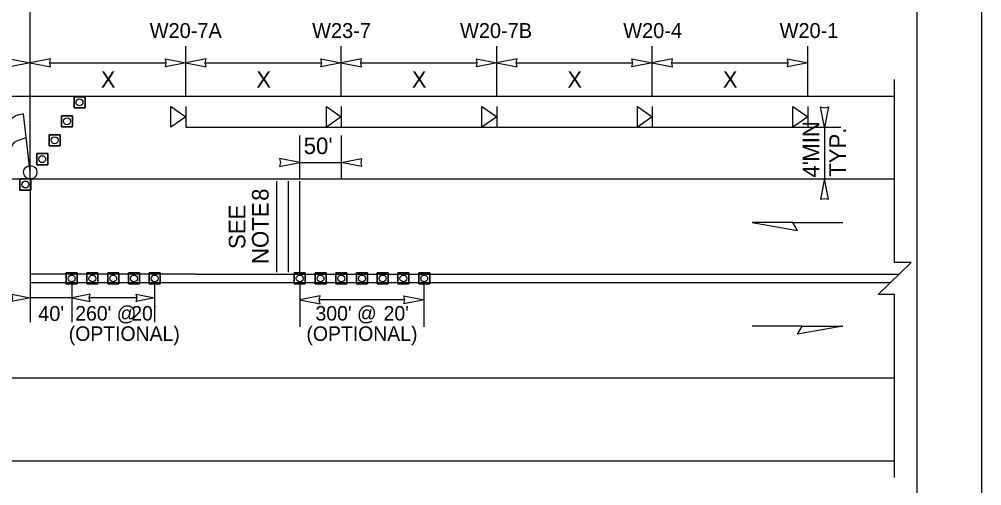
# Model space of a CAD drawing. Extents: x 99999.1 to 100095.7, y 99995 to 100010.7.
# Drawn here: x 100011.42 to 100016.062, y 100005.612 to 100007.863 of the extents above; entities that cross this region are included whole.
import ezdxf

# ---------------------------------------------------------------- set-up
doc = ezdxf.new("R2010")
doc.units = 0
for name, color, linetype in [('RD_ED_ShoulderPavedEdge', 7, 'Continuous'), ('RD_MK_LineDblYellowCenter', 7, 'Continuous'), ('RD_MK_LineEdgeWhite', 7, 'Continuous'), ('RD_MK_LineNoPass', 7, 'Continuous'), ('RD_MK_LineSkipCenter', 7, 'Continuous'), ('SH_GI_PlotLimits', 7, 'Continuous'), ('SH_GI_SheetBorder', 7, 'Continuous'), ('TR_SN_ConstructionSigns', 7, 'Continuous'), ('TR_WZ_FlaggingStation', 7, 'Continuous'), ('TR_WZ_PortableSignMountBlk-Org', 7, 'Continuous'), ('TR_WZ_TrafficCone', 7, 'Continuous'), ('TR_WZ_WorkZoneDetails', 7, 'Continuous'), ('TR_WZ_WorkZoneTextCurrent', 7, 'Continuous')]:
    doc.layers.add(name, color=color, linetype=linetype)

msp = doc.modelspace()

# ---------------------------------------------------------------- linework, layer by layer
at = {"layer": 'RD_ED_ShoulderPavedEdge'}
for p, q in [((100000.1076, 100007.4923), (100015.6424, 100007.4923)), ((100000.1076, 100005.7323), (100015.6424, 100005.7323))]:
    msp.add_line(p, q, dxfattribs=at)
at = {"layer": 'RD_MK_LineDblYellowCenter'}
for p, q in [((100012.2733, 100006.6323), (100015.6631, 100006.6323)), ((100012.2733, 100006.5923), (100015.6218, 100006.5923))]:
    msp.add_line(p, q, dxfattribs=at)
at = {"layer": 'RD_MK_LineEdgeWhite'}
for p, q in [((100000.1076, 100007.0923), (100015.6424, 100007.0923)), ((100000.1076, 100006.1323), (100015.6424, 100006.1323))]:
    msp.add_line(p, q, dxfattribs=at)
at = {"layer": 'RD_MK_LineNoPass'}
msp.add_line((100011.4733, 100006.5923), (100012.2733, 100006.5923), dxfattribs=at)
at = {"layer": 'RD_MK_LineSkipCenter'}
msp.add_lwpolyline([(100012.2733, 100006.6323), (100011.4733, 100006.6323)], dxfattribs=at)
at = {"layer": 'SH_GI_PlotLimits'}
msp.add_lwpolyline([(99999.0625, 99999.6875), (100016.0625, 99999.6875), (100016.0625, 100010.6875), (99999.0625, 100010.6875)], close=True, dxfattribs=at)
at = {"layer": 'SH_GI_SheetBorder'}
msp.add_line((100015.75, 100010.375), (100015.75, 100000), dxfattribs=at)
at = {"layer": 'TR_WZ_FlaggingStation'}
for p, q in [((100011.4543, 100007.2917), (100011.4413, 100007.4061)), ((100011.4733, 100007.1248), (100011.4413, 100007.4058)), ((100011.4543, 100007.2917), (100011.4543, 100007.2917))]:
    msp.add_line(p, q, dxfattribs=at)
for points in [[(100011.4413, 100007.4061), (100011.4355, 100007.4048), (100011.4177, 100007.4014), (100011.4039, 100007.3972), (100011.3942, 100007.3911), (100011.3857, 100007.3864), (100011.38, 100007.3796), (100011.3757, 100007.3717), (100011.3752, 100007.3655), (100011.3698, 100007.3563), (100011.359, 100007.3489), (100011.3466, 100007.3437), (100011.3233, 100007.3383)], [(100011.3366, 100007.2211), (100011.3448, 100007.2225), (100011.3624, 100007.2271), (100011.3781, 100007.2376), (100011.3846, 100007.2482), (100011.3885, 100007.2585), (100011.3976, 100007.2694), (100011.4086, 100007.2756), (100011.4259, 100007.2827), (100011.4543, 100007.2917)]]:
    msp.add_lwpolyline(points, dxfattribs=at)
msp.add_circle((100011.4733, 100007.1248), 0.0325, dxfattribs=at)
at = {"layer": 'TR_WZ_PortableSignMountBlk-Org'}
for p, q in [((100012.2233, 100007.4422), (100012.2233, 100007.3422)), ((100012.9733, 100007.4422), (100012.9733, 100007.3422)), ((100013.7233, 100007.4422), (100013.7233, 100007.3422)), ((100014.4733, 100007.4422), (100014.4733, 100007.3422)), ((100015.2233, 100007.4422), (100015.2233, 100007.3422))]:
    msp.add_line(p, q, dxfattribs=at)
for points in [[(100012.2233, 100007.3923), (100012.1515, 100007.3422), (100012.1515, 100007.4422)], [(100012.9733, 100007.3923), (100012.9015, 100007.3422), (100012.9015, 100007.4422)], [(100013.7233, 100007.3923), (100013.6515, 100007.3422), (100013.6515, 100007.4422)], [(100014.4733, 100007.3923), (100014.4015, 100007.3422), (100014.4015, 100007.4422)], [(100015.2233, 100007.3923), (100015.1515, 100007.3422), (100015.1515, 100007.4422)]]:
    msp.add_lwpolyline(points, close=True, dxfattribs=at)
at = {"layer": 'TR_WZ_TrafficCone'}
for points in [[(100011.6843, 100007.4886), (100011.7376, 100007.4886), (100011.7376, 100007.4352), (100011.6843, 100007.4352), (100011.6843, 100007.4886)], [(100011.6843, 100007.4352), (100011.7376, 100007.4352), (100011.7376, 100007.4886), (100011.6843, 100007.4886), (100011.6843, 100007.4352)], [(100011.6243, 100007.3972), (100011.6776, 100007.3972), (100011.6776, 100007.3439), (100011.6243, 100007.3439), (100011.6243, 100007.3972)], [(100011.6243, 100007.3439), (100011.6776, 100007.3439), (100011.6776, 100007.3972), (100011.6243, 100007.3972), (100011.6243, 100007.3439)], [(100011.5643, 100007.3059), (100011.6176, 100007.3059), (100011.6176, 100007.2526), (100011.5643, 100007.2526), (100011.5643, 100007.3059)], [(100011.5643, 100007.2526), (100011.6176, 100007.2526), (100011.6176, 100007.3059), (100011.5643, 100007.3059), (100011.5643, 100007.2526)], [(100011.5043, 100007.2146), (100011.5576, 100007.2146), (100011.5576, 100007.1612), (100011.5043, 100007.1612), (100011.5043, 100007.2146)], [(100011.5043, 100007.1612), (100011.5576, 100007.1612), (100011.5576, 100007.2146), (100011.5043, 100007.2146), (100011.5043, 100007.1612)], [(100011.4766, 100007.0923), (100011.4233, 100007.0923), (100011.4233, 100007.039), (100011.4766, 100007.039), (100011.4766, 100007.0923)], [(100011.4766, 100007.039), (100011.4233, 100007.039), (100011.4233, 100007.0923), (100011.4766, 100007.0923), (100011.4766, 100007.039)], [(100011.7, 100006.639), (100011.6467, 100006.639), (100011.6467, 100006.5857), (100011.7, 100006.5857), (100011.7, 100006.639)], [(100011.7, 100006.5857), (100011.6467, 100006.5857), (100011.6467, 100006.639), (100011.7, 100006.639), (100011.7, 100006.5857)], [(100011.8, 100006.639), (100011.7467, 100006.639), (100011.7467, 100006.5857), (100011.8, 100006.5857), (100011.8, 100006.639)], [(100011.8, 100006.5857), (100011.7467, 100006.5857), (100011.7467, 100006.639), (100011.8, 100006.639), (100011.8, 100006.5857)], [(100011.9, 100006.639), (100011.8467, 100006.639), (100011.8467, 100006.5857), (100011.9, 100006.5857), (100011.9, 100006.639)], [(100011.9, 100006.5857), (100011.8467, 100006.5857), (100011.8467, 100006.639), (100011.9, 100006.639), (100011.9, 100006.5857)], [(100012, 100006.639), (100011.9467, 100006.639), (100011.9467, 100006.5857), (100012, 100006.5857), (100012, 100006.639)], [(100012, 100006.5857), (100011.9467, 100006.5857), (100011.9467, 100006.639), (100012, 100006.639), (100012, 100006.5857)], [(100012.1, 100006.639), (100012.0467, 100006.639), (100012.0467, 100006.5857), (100012.1, 100006.5857), (100012.1, 100006.639)], [(100012.1, 100006.5857), (100012.0467, 100006.5857), (100012.0467, 100006.639), (100012.1, 100006.639), (100012.1, 100006.5857)], [(100012.8, 100006.5857), (100012.7467, 100006.5857), (100012.7467, 100006.639), (100012.8, 100006.639), (100012.8, 100006.5857)], [(100012.8, 100006.639), (100012.7467, 100006.639), (100012.7467, 100006.5857), (100012.8, 100006.5857), (100012.8, 100006.639)], [(100012.9, 100006.5857), (100012.8467, 100006.5857), (100012.8467, 100006.639), (100012.9, 100006.639), (100012.9, 100006.5857)], [(100012.9, 100006.639), (100012.8467, 100006.639), (100012.8467, 100006.5857), (100012.9, 100006.5857), (100012.9, 100006.639)], [(100013, 100006.5857), (100012.9467, 100006.5857), (100012.9467, 100006.639), (100013, 100006.639), (100013, 100006.5857)], [(100013, 100006.639), (100012.9467, 100006.639), (100012.9467, 100006.5857), (100013, 100006.5857), (100013, 100006.639)], [(100013.1, 100006.5857), (100013.0467, 100006.5857), (100013.0467, 100006.639), (100013.1, 100006.639), (100013.1, 100006.5857)], [(100013.1, 100006.639), (100013.0467, 100006.639), (100013.0467, 100006.5857), (100013.1, 100006.5857), (100013.1, 100006.639)], [(100013.2, 100006.5857), (100013.1467, 100006.5857), (100013.1467, 100006.639), (100013.2, 100006.639), (100013.2, 100006.5857)], [(100013.2, 100006.639), (100013.1467, 100006.639), (100013.1467, 100006.5857), (100013.2, 100006.5857), (100013.2, 100006.639)], [(100013.3, 100006.5857), (100013.2467, 100006.5857), (100013.2467, 100006.639), (100013.3, 100006.639), (100013.3, 100006.5857)], [(100013.3, 100006.639), (100013.2467, 100006.639), (100013.2467, 100006.5857), (100013.3, 100006.5857), (100013.3, 100006.639)], [(100013.4, 100006.5857), (100013.3467, 100006.5857), (100013.3467, 100006.639), (100013.4, 100006.639), (100013.4, 100006.5857)], [(100013.4, 100006.639), (100013.3467, 100006.639), (100013.3467, 100006.5857), (100013.4, 100006.5857), (100013.4, 100006.639)]]:
    msp.add_lwpolyline(points, dxfattribs=at)
for centre in [(100011.7109, 100007.4619), (100011.6509, 100007.3706), (100011.5909, 100007.2792), (100011.5309, 100007.1879), (100011.45, 100007.0657), (100011.6733, 100006.6123), (100011.7733, 100006.6123), (100011.8733, 100006.6123), (100011.9733, 100006.6123), (100012.0733, 100006.6123), (100012.7733, 100006.6123), (100012.8733, 100006.6123), (100012.9733, 100006.6123), (100013.0733, 100006.6123), (100013.1733, 100006.6123), (100013.2733, 100006.6123), (100013.3733, 100006.6123)]:
    msp.add_circle(centre, 0.0167, dxfattribs=at)
at = {"layer": 'TR_WZ_WorkZoneDetails'}
for p, q in [((100011.4733, 100007.0923), (100011.4733, 100008.9491)), ((100012.2233, 100007.4923), (100012.2233, 100007.7323)), ((100012.9733, 100007.4923), (100012.9733, 100007.7323)), ((100013.7233, 100007.4923), (100013.7233, 100007.7323)), ((100014.4733, 100007.4923), (100014.4733, 100007.7323)), ((100015.2233, 100007.4921), (100015.2233, 100007.7323)), ((100011.5671, 100007.6523), (100012.1296, 100007.6523)), ((100012.3171, 100007.6523), (100012.8796, 100007.6523)), ((100013.0671, 100007.6523), (100013.6296, 100007.6523)), ((100013.8171, 100007.6523), (100014.3796, 100007.6523)), ((100014.5671, 100007.6523), (100015.1296, 100007.6523)), ((100012.2233, 100007.3422), (100015.2233, 100007.3422)), ((100015.2233, 100007.3422), (100015.3833, 100007.3422)), ((100015.3033, 100007.3422), (100015.3033, 100007.0923)), ((100012.7733, 100007.0923), (100012.7733, 100007.3023)), ((100012.9733, 100007.3023), (100012.9733, 100007.0923)), ((100012.7733, 100007.1723), (100012.9733, 100007.1723)), ((100011.4733, 100007.0923), (100011.4733, 100006.4023)), ((100015.2233, 100007.0923), (100015.3833, 100007.0923)), ((100012.6628, 100006.6423), (100012.6628, 100007.0823)), ((100012.7185, 100006.6423), (100012.7185, 100007.0823)), ((100012.7733, 100006.6423), (100012.7733, 100007.0823)), ((100015.1513, 100006.8816), (100015.3924, 100006.8816)), ((100011.6733, 100006.5857), (100011.6733, 100006.4023)), ((100012.0733, 100006.5857), (100012.0733, 100006.4023)), ((100012.7733, 100006.589), (100012.7733, 100006.379)), ((100013.3733, 100006.379), (100013.3733, 100006.589)), ((100011.6733, 100006.5193), (100011.4733, 100006.5193)), ((100011.989, 100006.5193), (100011.7577, 100006.5193)), ((100013.2796, 100006.509), (100012.8671, 100006.509)), ((100015.1959, 100006.3816), (100014.9548, 100006.3816))]:
    msp.add_line(p, q, dxfattribs=at)
for points in [[(100011.4733, 100007.6523), (100011.3751, 100007.6331), (100011.3796, 100007.6523), (100011.3751, 100007.6716)], [(100011.4733, 100007.6523), (100011.5716, 100007.6331), (100011.5671, 100007.6523), (100011.5716, 100007.6716)], [(100012.2233, 100007.6523), (100012.1251, 100007.6331), (100012.1296, 100007.6523), (100012.1251, 100007.6716)], [(100012.2233, 100007.6523), (100012.3216, 100007.6331), (100012.3171, 100007.6523), (100012.3216, 100007.6716)], [(100012.9733, 100007.6523), (100012.8751, 100007.6331), (100012.8796, 100007.6523), (100012.8751, 100007.6716)], [(100012.9733, 100007.6523), (100013.0716, 100007.6331), (100013.0671, 100007.6523), (100013.0716, 100007.6716)], [(100013.7233, 100007.6523), (100013.6251, 100007.6331), (100013.6296, 100007.6523), (100013.6251, 100007.6716)], [(100013.7233, 100007.6523), (100013.8216, 100007.6331), (100013.8171, 100007.6523), (100013.8216, 100007.6716)], [(100014.4733, 100007.6523), (100014.3751, 100007.6331), (100014.3796, 100007.6523), (100014.3751, 100007.6716)], [(100014.4733, 100007.6523), (100014.5716, 100007.6331), (100014.5671, 100007.6523), (100014.5716, 100007.6716)], [(100015.2233, 100007.6523), (100015.1251, 100007.6331), (100015.1296, 100007.6523), (100015.1251, 100007.6716)], [(100015.3033, 100007.3422), (100015.2841, 100007.4405), (100015.3033, 100007.436), (100015.3226, 100007.4405)], [(100012.7733, 100007.1723), (100012.6751, 100007.1916), (100012.6796, 100007.1723), (100012.6751, 100007.1531)], [(100012.9733, 100007.1723), (100013.0716, 100007.1916), (100013.0671, 100007.1723), (100013.0716, 100007.1531)], [(100015.3033, 100007.0923), (100015.2841, 100006.9941), (100015.3033, 100006.9986), (100015.3226, 100006.9941)], [(100014.9548, 100006.8816), (100015.1736, 100006.843), (100015.1513, 100006.8816)], [(100011.4733, 100006.5193), (100011.3849, 100006.502), (100011.389, 100006.5193), (100011.3849, 100006.5367)], [(100011.6733, 100006.5193), (100011.7618, 100006.502), (100011.7577, 100006.5193), (100011.7618, 100006.5367)], [(100012.0733, 100006.5193), (100011.9849, 100006.502), (100011.989, 100006.5193), (100011.9849, 100006.5367)], [(100012.7733, 100006.509), (100012.8716, 100006.4897), (100012.8671, 100006.509), (100012.8716, 100006.5283)], [(100013.3733, 100006.509), (100013.2751, 100006.4897), (100013.2796, 100006.509), (100013.2751, 100006.5283)], [(100015.3924, 100006.3816), (100015.1736, 100006.343), (100015.1959, 100006.3816)]]:
    msp.add_lwpolyline(points, close=True, dxfattribs=at)
msp.add_lwpolyline([(100015.6424, 100005.6523), (100015.6424, 100006.5349), (100015.5624, 100006.5349), (100015.7225, 100006.6898), (100015.6424, 100006.6898), (100015.6424, 100007.5723)], dxfattribs=at)

# ---------------------------------------------------------------- texts
at = {"layer": 'TR_SN_ConstructionSigns'}
for s, p in [('W20-7A', (100012.0494, 100007.7723)), ('W23-7', (100012.8328, 100007.7723)), ('W20-7B', (100013.546, 100007.7723)), ('W20-4', (100014.3334, 100007.7723)), ('W20-1', (100015.0875, 100007.7723))]:
    msp.add_text(s, height=0.072, rotation=360, dxfattribs=at).set_placement(p)
at = {"layer": 'TR_WZ_WorkZoneDetails'}
for s, p in [('8', (100012.6228, 100006.9868)), ('SEE', (100012.5108, 100006.7544)), ('NOTE', (100012.6228, 100006.682))]:
    msp.add_text(s, height=0.08, rotation=90, dxfattribs=at).set_placement(p)
at = {"layer": 'TR_WZ_WorkZoneTextCurrent'}
for s, height, p in [('X', 0.08, (100011.8136, 100007.5323)), ('X', 0.08, (100012.5636, 100007.5323)), ('X', 0.08, (100013.3136, 100007.5323)), ('X', 0.08, (100014.0636, 100007.5323)), ('X', 0.08, (100014.8136, 100007.5323)), ("50'", 0.08, (100012.7921, 100007.2123)), ("40'", 0.072, (100011.5114, 100006.4073)), ("260' @", 0.07, (100011.6903, 100006.4093)), ("20'", 0.07, (100011.9604, 100006.4093)), ("300' @", 0.07, (100012.8491, 100006.4093)), ("20'", 0.07, (100013.1775, 100006.4093)), ('(OPTIONAL)', 0.07, (100011.659, 100006.3113)), ('(OPTIONAL)', 0.07, (100012.8053, 100006.3113))]:
    msp.add_text(s, height=height, dxfattribs=at).set_placement(p)
for s, p in [('MIN', (100015.2793, 100007.1754)), ('TYP.', (100015.4073, 100007.1026)), ("4'", (100015.2793, 100007.0989))]:
    msp.add_text(s, height=0.08, rotation=90, dxfattribs=at).set_placement(p)

doc.saveas('drawing.dxf')
